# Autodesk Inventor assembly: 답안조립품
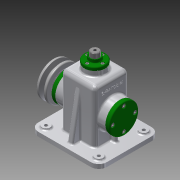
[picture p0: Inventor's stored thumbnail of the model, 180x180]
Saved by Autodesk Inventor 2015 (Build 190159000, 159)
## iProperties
Created: 2016-02
Part Number: 답안조립품
Document SubType Name: Assembly
Designer: Administrator
Author: Administrator
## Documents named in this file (19)
- C:\Users\Administrator\Desktop\460219V1009\답안조립품.iam
- C:\Users\Administrator\Desktop\460219V1009\본체.ipt
- C:\Users\Administrator\Desktop\460219V1009\V-벨트풀리.ipt
- C:\Users\Administrator\Desktop\460219V1009\고정핀.ipt
- C:\Users\Administrator\Desktop\460219V1009\뒤커버.ipt
- C:\Users\Administrator\Desktop\460219V1009\링크.ipt
- C:\Users\Administrator\Desktop\460219V1009\멈춤링 6 x 5.ipt
- C:\Users\Administrator\Desktop\460219V1009\멈춤링 15 x 1.ipt
- C:\Users\Administrator\Desktop\460219V1009\베어링 15 x 35 x 11.ipt
- C:\Users\Administrator\Desktop\460219V1009\볼트 M3 x 8.ipt
- C:\Users\Administrator\Desktop\460219V1009\볼트 M4 x 10.ipt
- C:\Users\Administrator\Desktop\460219V1009\볼트 M6 x 12.ipt
- C:\Users\Administrator\Desktop\460219V1009\상부부시.ipt
- C:\Users\Administrator\Desktop\460219V1009\슬라이드바.ipt
- C:\Users\Administrator\Desktop\460219V1009\앞커버.ipt
- C:\Users\Administrator\Desktop\460219V1009\오일실 15 25 7.ipt
- C:\Users\Administrator\Desktop\460219V1009\와셔.ipt
- C:\Users\Administrator\Desktop\460219V1009\키 5 x 5 x 14.ipt
- C:\Users\Administrator\Desktop\460219V1009\편심축.ipt
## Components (15 placed, 5 different names)
1. V-벨트풀리:1
2. 고정핀:1
3. ISO 4762 M3 x 8:1
4. ISO 4762 M4 x 10:1
5. ISO 4018 M6 x 12:1
6. ISO 4762 M4 x 10:2
7. ISO 4762 M4 x 10:3
8. ISO 4762 M4 x 10:4
9. ISO 4762 M4 x 10:5
10. ISO 4762 M4 x 10:6
11. ISO 4762 M4 x 10:7
12. ISO 4762 M4 x 10:8
13. ISO 4762 M3 x 8:2
14. ISO 4762 M3 x 8:3
15. ISO 4762 M3 x 8:4
